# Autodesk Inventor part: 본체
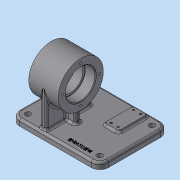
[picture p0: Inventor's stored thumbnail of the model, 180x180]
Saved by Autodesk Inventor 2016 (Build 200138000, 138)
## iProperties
Created: 2019-09
Part Number: 본체
Material: 알루미늄 6061
Document SubType Name: Modeling
Designer: mduedu
Density: 2.71 g/cm^3
Mass: 561.398 g
Surface Area: 499.749 cm^2
Volume: 207.158 cm^3
Appearance: 기본값
Author: mduedu
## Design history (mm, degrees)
sketch "스케치1"
  geometry: L1 (42, -62)-(-84, -62); L2 (-84, -62)-(-84, 36); L3 (-84, 36)-(42, 36); L4 (42, 36)-(42, -62); 1 further point
  constraints: 8 end point, 2 parallel, 1 horizontal, 1 perpendicular
  dimensions: "d0" = 36 distance from line of L3 point (0, 0); "d1" = 98 distance of L1.end L2.end; "d2" = 42 distance from line of L4 point (0, 0); "d3" = 126 distance of L2.end L3.end
extrude "돌출1" new body sketch "스케치1" distance "d4" = 9; taper "d5" = 0 deg
sketch "스케치2"
  geometry: L1 (0, -62)-(0, 36) reference; C1 r 32 at (59, 0); 1 further point
  constraints: 1 centre point, 1 horizontal alignment
  dimensions: "d6" = 64 diameter of C1; "d7" = 59 distance from line of L1 C1.centre
extrude "돌출2" join sketch "스케치2" stored distance "d8" = 42; taper "d9" = 0 deg
sketch "스케치3"
  geometry: L1 (-17, 4)-(17, 4); L2 (17, 4)-(17, -4); L3 (17, -4)-(-17, -4); L4 (-17, -4)-(-17, 4); L5 (-4, 32)-(4, 32); L6 (4, 32)-(4, -32); L7 (4, -32)-(-4, -32); L8 (-4, -32)-(-4, 32); 5 further points
  constraints: 16 end point, 4 midpoint, 4 parallel, 2 horizontal, 2 horizontal alignment, 2 perpendicular, 2 vertical alignment
  dimensions: "d10" = 8 distance of L5.start L5.end; "d12" = 8 distance of L1.end L2.end; "d13" = 34 distance of L2.end L3.end; "d14" = 64 distance of L5.end L6.end
extrude "돌출3" join sketch "스케치3" stored distance "d15" = 42; taper "d16" = 0 deg
sketch "스케치4"
  geometry: C1 r 32 at (0, 0) reference; C2 r 21 at (0, 0); 1 further point
  constraints: 1 centre point, 1 coincident
  dimensions: "d17" = 42 diameter of C2
extrude "돌출4" cut sketch "스케치4" distance "d18" = 15; taper "d19" = 0 deg
hole "구멍1" diameter "d22" = 36; stored, may be unused: countersink angle "d26" = 90 deg, drill point angle "d28" = 118 deg; dims "d20" = 10, "d21" = 10, "d23" = 6, "d24" = 4, "d25" = 2, "d27" = 8
fillet "모깎기1" dims "d29" = 0.3
chamfer "모따기1" distance "d30" = 1; stored, may be unused: second distance "d31" = 2, angle "d32" = 45 deg
sketch "스케치5" dims "d33" = 52
  geometry: C1 r 32 at (0, 0) reference; 3 further points
  constraints: 2 vertical alignment, 1 coincident, 2 other
hole "구멍2" sketch "스케치5" at (0, 26) diameter "d34" = 3.242; stored, may be unused: countersink angle "d38" = 90 deg, drill point angle "d40" = 118 deg; dims "d35" = 8, "d36" = 4, "d37" = 2, "d39" = 10
fillet "모깎기2" dims "d44" = 12
sketch "스케치6"
  geometry: L1 (-42, 50)-(-42, -24) reference; L2 (-30, -36)-(72, -36) reference; L3 (84, -24)-(84, 50) reference; L4 (72, 62)-(-30, 62) reference; L5 (17, 4)-(17, -4) reference; L6 (17, -4)-(4, -4) reference; L7 (4, -4)-(4, -32) reference; L8 (4, -32)-(-4, -32) reference; L9 (-4, -32)-(-4, -4) reference; L10 (-4, -4)-(-17, -4) reference; L11 (-17, -4)-(-17, 4) reference; L12 (-17, 4)-(-4, 4) reference; L13 (-4, 4)-(-4, 32) reference; L14 (-4, 32)-(4, 32) reference; L15 (4, 32)-(4, 4) reference; L16 (4, 4)-(17, 4) reference; A1 r 12 centre (-30, 50) between (-30, 62) and (-42, 50) reference; A2 r 12 centre (-30, -24) between (-42, -24) and (-30, -36) reference; A3 r 12 centre (72, -24) between (72, -36) and (84, -24) reference; A4 r 12 centre (72, 50) between (84, 50) and (72, 62) reference; 5 further points
  constraints: 4 coincident
hole "구멍3" sketch "스케치6" at (-30, 50), (72, 50), (72, -24), (-30, -24) diameter "d45" = 8; stored, may be unused: countersink angle "d49" = 90 deg, drill point angle "d51" = 118 deg; dims "d46" = 8, "d47" = 4, "d48" = 2, "d50" = 10
sketch "스케치7"
  geometry: L1 (38, 57)-(58, 57); L2 (58, 57)-(58, 17); L3 (58, 17)-(38, 17); L4 (38, 17)-(38, 57); L5 (72, 62)-(-30, 62) reference; 3 further points
  constraints: 8 end point, 2 midpoint, 2 parallel, 1 horizontal, 1 perpendicular
  dimensions: "d52" = 48 horizontal distance of point (48, 57) point (0, 0); "d53" = 20 distance of L1.start L1.end; "d54" = 40 distance of L1.end L2.end; "d55" = 25 distance from line of point (38, 37) L5
extrude "돌출5" join sketch "스케치7" distance "d56" = 3; taper "d57" = 0 deg
fillet "모깎기3" dims "d58" = 3
fillet "모깎기4" dims "d59" = 3
fillet "모깎기5" dims "d60" = 3
fillet "모깎기6" dims "d61" = 3
fillet "모깎기7" dims "d62" = 3
fillet "모깎기8" dims "d63" = 3
sketch "스케치8"
  geometry: L1 (72, 62)-(58.317, 62) reference; L2 (84, -24)-(84, 50) reference; C1 r 1.5 at (43, 53); C2 r 1.5 at (53, 21); 1 further point
  constraints: 2 centre point, 1 equal radius
  dimensions: "d64" = 3 diameter of C1; "d65" = 9 distance from line of C1.centre L1; "d66" = 32 vertical distance of C2.centre C1.centre; "d67" = 10 horizontal distance of C2.centre C1.centre; "d68" = 31 distance from line of L2 C2.centre
hole "구멍4" sketch "스케치8" at (43, 53), (53, 21) diameter "d69" = 3; stored, may be unused: countersink angle "d73" = 90 deg, drill point angle "d75" = 118 deg; dims "d70" = 8, "d71" = 4, "d72" = 2, "d74" = 6
sketch "스케치9"
  geometry: C1 r 1.5 at (43, 53) reference; C2 r 1.5 at (53, 21) reference; 3 further points
  constraints: 2 horizontal alignment, 2 vertical alignment
hole "구멍5" sketch "스케치9" at (53, 53), (43, 21) diameter "d76" = 3.242; stored, may be unused: countersink angle "d80" = 90 deg, drill point angle "d82" = 118 deg; dims "d77" = 6, "d78" = 4, "d79" = 2, "d81" = 8
sketch "스케치10"
  geometry: L1 (-30, -36)-(72, -36) reference; L2 (84, -24)-(84, 50) reference; 2 further points
  constraints: 1 other
  dimensions: "d83" = 10 distance from line of point (46, -26) L1; "d84" = 38 distance from line of point (46, -26) L2
feature "엠보싱1" sketch "스케치10" dims "d0" = 36, "d1" = 98, "d2" = 42, "d3" = 126, "d10" = 8, "d14" = 64, "d85" = 0.5, "d86" = 0
node "솔리드1"
mirror "대칭1"
pattern_circular "원형 패턴1" dims angle "d42" = 360 deg
mirror "대칭2"
node "투영된 루프1"
